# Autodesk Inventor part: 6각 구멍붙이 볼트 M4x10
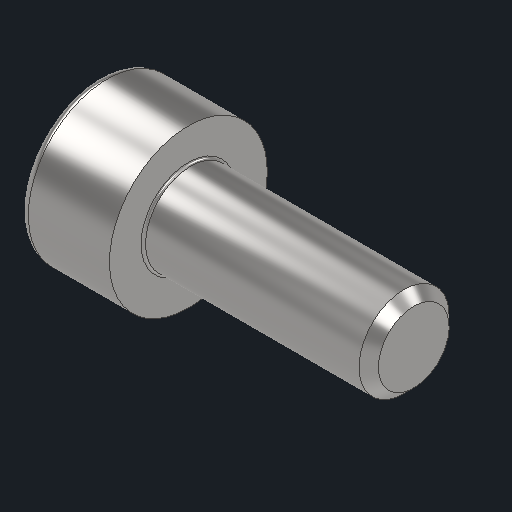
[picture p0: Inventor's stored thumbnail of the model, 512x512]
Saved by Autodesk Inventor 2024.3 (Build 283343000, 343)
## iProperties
Created: 2025-07
Part Number: 6각 구멍붙이 볼트 M4x10
Material: 강철, 연강
Description: 6각머리 태핑 나사
Document SubType Name: Modeling
Designer: user
Density: 7.85 g/cm^3
Appearance: 기본값
Author: jhkim
Sending System: Autodesk Inventor 2026
Preprocessor: ST-DEVELOPER v20.1
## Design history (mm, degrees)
feature "Solid1"
node "솔리드1"
